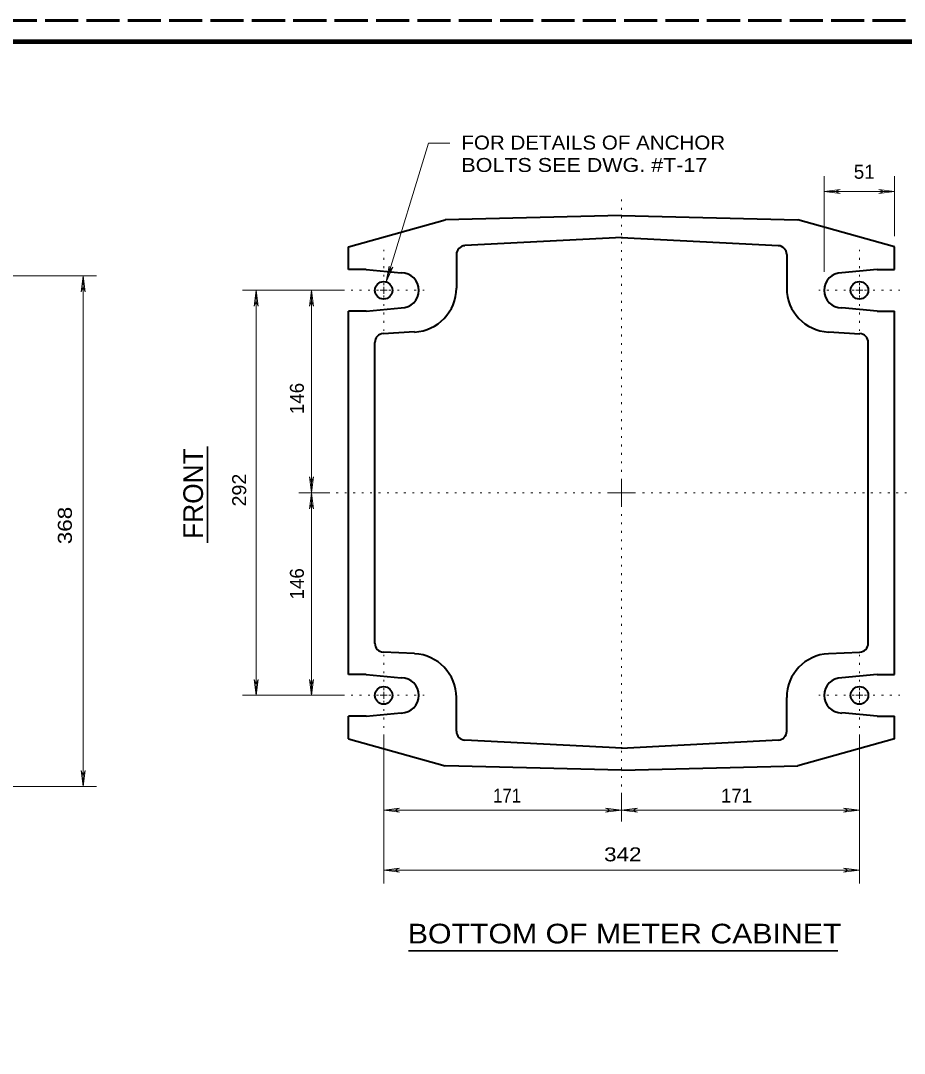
# Model space of a CAD drawing. Extents: x 312583 to 312853, y 144419 to 144586.
# Drawn here: x 312668.6 to 312716.7, y 144530 to 144586.2 of the extents above; entities that cross this region are included whole.
import ezdxf
from ezdxf.enums import TextEntityAlignment as Align

# ---------------------------------------------------------------- set-up
doc = ezdxf.new("R2010")
doc.units = 0
doc.header["$LTSCALE"] = 0.3
doc.linetypes.add('DOTTED', pattern=[1.5, 0.3, -1.2])
doc.linetypes.add('LONG_DASHED', pattern=[7.5, 6, -1.5])
for name, color, linetype, lineweight in [('1', 7, 'Continuous', 40), ('2', 7, 'Continuous', 13), ('63', 7, 'LONG_DASHED', 60)]:
    doc.layers.add(name, color=color, linetype=linetype, lineweight=lineweight)

msp = doc.modelspace()

# ---------------------------------------------------------------- linework, layer by layer
at = {"layer": '1'}
for p, q in [((312701.3008, 144575.6233), (312691.7175, 144575.3856)), ((312701.3008, 144575.6233), (312710.8842, 144575.3856)), ((312686.4505, 144573.9213), (312691.7175, 144575.3856)), ((312716.1588, 144573.9213), (312710.8842, 144575.3856)), ((312701.3315, 144574.4273), (312692.7755, 144573.9826)), ((312701.2778, 144574.4273), (312709.8338, 144573.9826)), ((312686.4505, 144572.6793), (312686.4505, 144573.9213)), ((312716.1588, 144572.6793), (312716.1588, 144573.9213)), ((312692.3232, 144573.4996), (312692.3232, 144571.6749)), ((312710.2862, 144573.4996), (312710.2862, 144571.6749)), ((312687.4088, 144572.6793), (312686.4505, 144572.6793)), ((312687.4088, 144572.6793), (312689.3255, 144572.5106)), ((312715.2005, 144572.6793), (312713.2838, 144572.5106)), ((312715.2005, 144572.6793), (312716.1588, 144572.6793)), ((312686.4505, 144550.6376), (312686.4505, 144570.4176)), ((312687.4088, 144570.4176), (312686.4505, 144570.4176)), ((312687.4088, 144570.4176), (312689.3255, 144570.5939)), ((312715.2005, 144570.4176), (312713.2838, 144570.5939)), ((312715.2005, 144570.4176), (312716.1588, 144570.4176)), ((312716.1588, 144550.6376), (312716.1588, 144570.4176)), ((312690.0462, 144569.2829), (312688.3442, 144569.1909)), ((312712.5632, 144569.2829), (312714.2652, 144569.1909)), ((312687.8842, 144552.3396), (312687.8842, 144568.7156)), ((312714.7175, 144552.3396), (312714.7175, 144568.7156)), ((312690.0462, 144551.7799), (312688.3442, 144551.8643)), ((312712.5632, 144551.7799), (312714.2652, 144551.8643)), ((312687.4088, 144550.6376), (312686.4505, 144550.6376)), ((312687.4088, 144550.6376), (312689.3255, 144550.4689)), ((312715.2005, 144550.6376), (312713.2838, 144550.4689)), ((312715.2005, 144550.6376), (312716.1588, 144550.6376)), ((312692.3232, 144547.5556), (312692.3232, 144549.3879)), ((312710.2862, 144547.5556), (312710.2862, 144549.3879)), ((312687.4088, 144548.3759), (312689.3255, 144548.5523)), ((312715.2005, 144548.3759), (312713.2838, 144548.5523)), ((312686.4505, 144547.1416), (312686.4505, 144548.3759)), ((312687.4088, 144548.3759), (312686.4505, 144548.3759)), ((312715.2005, 144548.3759), (312716.1588, 144548.3759)), ((312716.1588, 144547.1416), (312716.1588, 144548.3759)), ((312686.4505, 144547.1416), (312691.7175, 144545.6773)), ((312701.3315, 144546.6356), (312692.7755, 144547.0726)), ((312701.2778, 144546.6356), (312709.8338, 144547.0803)), ((312716.1588, 144547.1416), (312710.8842, 144545.6773)), ((312701.3008, 144545.4319), (312691.7175, 144545.6773)), ((312701.3008, 144545.4319), (312710.8842, 144545.6773))]:
    msp.add_line(p, q, dxfattribs=at)
at = {"layer": '1', "lineweight": 158}
msp.add_lwpolyline([(312616.5, 144423.1446), (312616.5, 144585.0846), (312849, 144585.0846)], dxfattribs=at)
at = {"layer": '1'}
for centre in [(312688.3653, 144571.5484), (312714.2403, 144571.5484), (312688.3653, 144549.5068), (312714.2403, 144549.5068)]:
    msp.add_circle(centre, 0.4792, dxfattribs=at)
for centre, radius, start, end in [((312692.7985, 144573.5001), 0.4792, 92.9765, 180), ((312709.807, 144573.5001), 0.4792, 0, 87.0235), ((312689.3236, 144571.5484), 0.9583, 270, 90), ((312713.2819, 144571.5484), 0.9583, 90, 270), ((312689.9235, 144571.6719), 2.3958, 272.86241, 0), ((312712.682, 144571.6719), 2.3958, 180, 267.13759), ((312688.3653, 144568.7153), 0.4792, 92.88828, 180), ((312714.2403, 144568.7153), 0.4792, 0, 87.11172), ((312688.3653, 144552.3399), 0.4792, 180, 267.11172), ((312714.2403, 144552.3399), 0.4792, 272.88828, 0), ((312689.9235, 144549.3833), 2.3958, 0, 87.13759), ((312712.682, 144549.3833), 2.3958, 92.86241, 180), ((312689.3236, 144549.5068), 0.9583, 270, 90), ((312713.2819, 144549.5068), 0.9583, 90, 270), ((312692.7985, 144547.5532), 0.4792, 180, 267.03604), ((312709.807, 144547.5551), 0.4792, 272.9765, 0)]:
    msp.add_arc(centre, radius, start, end, dxfattribs=at)
at = {"layer": '2'}
for p, q in [((312712.3255, 144572.5566), (312712.3255, 144577.7699)), ((312716.1588, 144574.5039), (312716.1588, 144577.7699)), ((312712.3255, 144576.9266), (312713.1918, 144577.0339)), ((312712.3255, 144576.9266), (312716.1588, 144576.9266)), ((312712.3255, 144576.9266), (312713.1918, 144576.8193)), ((312713.1918, 144577.0339), (312712.9158, 144576.9266)), ((312713.1918, 144576.8193), (312712.9158, 144576.9266)), ((312715.2925, 144577.0339), (312715.5685, 144576.9266)), ((312716.1588, 144576.9266), (312715.2925, 144577.0339)), ((312715.2925, 144576.8193), (312715.5685, 144576.9266)), ((312716.1588, 144576.9266), (312715.2925, 144576.8193)), ((312688.5052, 144572.0046), (312688.6585, 144572.8709)), ((312688.5052, 144572.0046), (312688.8578, 144572.8019)), ((312688.6585, 144572.8709), (312688.6815, 144572.5719)), ((312688.8578, 144572.8019), (312688.6815, 144572.5719)), ((312666.4834, 144572.3379), (312672.7471, 144572.3379)), ((312672.0264, 144572.3379), (312671.9191, 144571.4716)), ((312672.0264, 144544.5463), (312672.0264, 144572.3379)), ((312672.0264, 144572.3379), (312672.1338, 144571.4716)), ((312671.9191, 144571.4716), (312672.0264, 144571.7476)), ((312672.1338, 144571.4716), (312672.0264, 144571.7476)), ((312686.1592, 144571.5523), (312680.6852, 144571.5523)), ((312681.4365, 144571.5523), (312681.3292, 144570.6859)), ((312681.4365, 144549.5106), (312681.4365, 144571.5523)), ((312681.4365, 144571.5523), (312681.5438, 144570.6859)), ((312684.4342, 144571.5523), (312684.3268, 144570.6859)), ((312684.4342, 144571.5523), (312684.5415, 144570.6859)), ((312688.3672, 144571.5523), (312688.1755, 144571.5523)), ((312688.3672, 144571.5523), (312688.3672, 144571.7439)), ((312688.3672, 144571.5523), (312688.5588, 144571.5523)), ((312688.3672, 144571.5523), (312688.3672, 144571.3606)), ((312714.2422, 144571.5523), (312714.0505, 144571.5523)), ((312714.2422, 144571.5523), (312714.2422, 144571.7439)), ((312714.2422, 144571.5523), (312714.4338, 144571.5523)), ((312714.2422, 144571.5523), (312714.2422, 144571.3606)), ((312681.3292, 144570.6859), (312681.4365, 144570.9619)), ((312681.5438, 144570.6859), (312681.4365, 144570.9619)), ((312684.3268, 144570.6859), (312684.4342, 144570.9619)), ((312684.5415, 144570.6859), (312684.4342, 144570.9619)), ((312684.3268, 144561.3939), (312684.4342, 144561.1179)), ((312684.4342, 144560.5276), (312684.3268, 144561.3939)), ((312684.5415, 144561.3939), (312684.4342, 144561.1179)), ((312684.4342, 144560.5276), (312684.5415, 144561.3939)), ((312701.3008, 144560.5276), (312701.3008, 144561.2943)), ((312685.4385, 144560.5276), (312683.7518, 144560.5276)), ((312684.4342, 144560.5276), (312684.3268, 144559.6613)), ((312684.4342, 144560.5276), (312684.5415, 144559.6613)), ((312701.3008, 144560.5276), (312700.5342, 144560.5276)), ((312701.3008, 144560.5276), (312702.0675, 144560.5276)), ((312701.3008, 144560.5276), (312701.3008, 144559.7609)), ((312684.3268, 144559.6613), (312684.4342, 144559.9373)), ((312684.5415, 144559.6613), (312684.4342, 144559.9373)), ((312681.3292, 144550.3769), (312681.4365, 144550.1009)), ((312681.4365, 144549.5106), (312681.3292, 144550.3769)), ((312681.5438, 144550.3769), (312681.4365, 144550.1009)), ((312681.4365, 144549.5106), (312681.5438, 144550.3769)), ((312684.3268, 144550.3769), (312684.4342, 144550.1009)), ((312684.4342, 144549.5106), (312684.3268, 144550.3769)), ((312684.5415, 144550.3769), (312684.4342, 144550.1009)), ((312684.4342, 144549.5106), (312684.5415, 144550.3769)), ((312688.3672, 144549.5106), (312688.3672, 144549.7023)), ((312714.2422, 144549.5106), (312714.2422, 144549.7023)), ((312686.1592, 144549.5106), (312680.6852, 144549.5106)), ((312688.3672, 144549.5106), (312688.1755, 144549.5106)), ((312688.3672, 144549.5106), (312688.5588, 144549.5106)), ((312688.3672, 144549.5106), (312688.3672, 144549.3189)), ((312714.2422, 144549.5106), (312714.0505, 144549.5106)), ((312714.2422, 144549.5106), (312714.4338, 144549.5106)), ((312714.2422, 144549.5106), (312714.2422, 144549.3189)), ((312688.3672, 144547.3026), (312688.3672, 144539.2756)), ((312714.2422, 144547.3026), (312714.2422, 144539.2756)), ((312671.9191, 144545.4126), (312672.0264, 144545.1366)), ((312672.0264, 144544.5463), (312671.9191, 144545.4126)), ((312672.1338, 144545.4126), (312672.0264, 144545.1366)), ((312672.0264, 144544.5463), (312672.1338, 144545.4126)), ((312666.4834, 144544.5463), (312672.7471, 144544.5463)), ((312701.3008, 144544.1056), (312701.3008, 144542.6413)), ((312688.3672, 144543.2623), (312689.2335, 144543.3696)), ((312688.3672, 144543.2623), (312689.2335, 144543.1549)), ((312689.2335, 144543.3696), (312688.9575, 144543.2623)), ((312689.2335, 144543.1549), (312688.9575, 144543.2623)), ((312700.4345, 144543.3696), (312700.7105, 144543.2623)), ((312701.3008, 144543.2623), (312700.4345, 144543.3696)), ((312700.4345, 144543.1549), (312700.7105, 144543.2623)), ((312701.3008, 144543.2623), (312700.4345, 144543.1549)), ((312701.3008, 144543.2623), (312702.1672, 144543.3696)), ((312701.3008, 144543.2623), (312702.1672, 144543.1549)), ((312702.1672, 144543.3696), (312701.8912, 144543.2623)), ((312702.1672, 144543.1549), (312701.8912, 144543.2623)), ((312713.3758, 144543.3696), (312713.6518, 144543.2623)), ((312714.2422, 144543.2623), (312713.3758, 144543.3696)), ((312713.3758, 144543.1549), (312713.6518, 144543.2623)), ((312714.2422, 144543.2623), (312713.3758, 144543.1549)), ((312688.3672, 144539.9963), (312689.2335, 144540.1036)), ((312689.2335, 144540.1036), (312688.9575, 144539.9963)), ((312713.3758, 144540.1036), (312713.6518, 144539.9963)), ((312714.2422, 144539.9963), (312713.3758, 144540.1036)), ((312688.3672, 144539.9963), (312714.2422, 144539.9963)), ((312688.3672, 144539.9963), (312689.2335, 144539.8889)), ((312689.2335, 144539.8889), (312688.9575, 144539.9963)), ((312713.3758, 144539.8889), (312713.6518, 144539.9963)), ((312714.2422, 144539.9963), (312713.3758, 144539.8889))]:
    msp.add_line(p, q, dxfattribs=at)
at = {"layer": '2', "linetype": 'DOTTED'}
for p, q in [((312701.3008, 144561.6776), (312701.3008, 144576.7043)), ((312688.3672, 144571.8359), (312688.3672, 144573.7526)), ((312714.2422, 144571.8359), (312714.2422, 144573.7526)), ((312688.0758, 144571.5523), (312686.1592, 144571.5523)), ((312688.6508, 144571.5523), (312690.5675, 144571.5523)), ((312713.9508, 144571.5523), (312712.0342, 144571.5523)), ((312714.5258, 144571.5523), (312716.4425, 144571.5523)), ((312688.3672, 144571.2609), (312688.3672, 144569.3443)), ((312714.2422, 144571.2609), (312714.2422, 144569.3443)), ((312700.1508, 144560.5276), (312685.4385, 144560.5276)), ((312702.4508, 144560.5276), (312716.9715, 144560.5276)), ((312701.3008, 144559.3776), (312701.3008, 144544.1056)), ((312688.3672, 144549.7943), (312688.3672, 144551.7109)), ((312714.2422, 144549.7943), (312714.2422, 144551.7109)), ((312688.0758, 144549.5106), (312686.1592, 144549.5106)), ((312688.3672, 144549.2193), (312688.3672, 144547.3026)), ((312688.6508, 144549.5106), (312690.5675, 144549.5106)), ((312713.9508, 144549.5106), (312712.0342, 144549.5106)), ((312714.2422, 144549.2193), (312714.2422, 144547.3026)), ((312714.5258, 144549.5106), (312716.4425, 144549.5106))]:
    msp.add_line(p, q, dxfattribs=at)
at = {"layer": '2', "lineweight": 35}
for p, q in [((312678.7838, 144557.8136), (312678.7838, 144563.0499)), ((312689.7122, 144535.61), (312713.0632, 144535.61))]:
    msp.add_line(p, q, dxfattribs=at)
at = {"layer": '2'}
for points in [[(312688.5052, 144572.0046), (312690.8052, 144579.5639), (312691.9705, 144579.5639)], [(312684.4342, 144549.5106), (312684.4342, 144560.5276), (312684.4342, 144571.5523)], [(312688.3672, 144543.2623), (312701.3008, 144543.2623), (312714.2422, 144543.2623)]]:
    msp.add_lwpolyline(points, dxfattribs=at)
at = {"layer": '63'}
msp.add_line((312851.75, 144586.2246), (312583.526, 144586.2246), dxfattribs=at)

# ---------------------------------------------------------------- texts
at = {"layer": '2'}
for s, width, p in [('FOR DETAILS OF ANCHOR', 1.1, (312692.5915, 144579.2103)), ('BOLTS SEE DWG. #T-17', 1.15, (312692.5915, 144577.9903)), ('171', 0.9, (312694.3117, 144543.6716)), ('342 ', 1.2, (312700.3553, 144540.4764))]:
    msp.add_text(s, height=0.76, dxfattribs=dict(at, width=width)).set_placement(p)
for s, p in [('51 ', (312713.9366, 144577.6195)), ('171 ', (312706.7095, 144543.6716))]:
    msp.add_text(s, height=0.76, dxfattribs=at).set_placement(p)
for p in [(312684.0255, 144564.8164), (312684.0255, 144554.733)]:
    msp.add_text('146', height=0.76, rotation=90, dxfattribs=at).set_placement(p)
msp.add_text('FRONT', height=1.07, rotation=90, dxfattribs=at).set_placement((312678.5376, 144560.488), align=Align.CENTER)
for s, width, p in [('292', 1.05, (312680.8861, 144559.7884)), ('368 ', 1.2, (312671.4051, 144557.7343))]:
    msp.add_text(s, height=0.76, rotation=90, dxfattribs=dict(at, width=width)).set_placement(p)
at = {"layer": '2', "width": 1.15}
msp.add_text('BOTTOM OF METER CABINET', height=1.07, dxfattribs=at).set_placement((312701.4706, 144536.0102), align=Align.CENTER)

doc.saveas('drawing.dxf')
